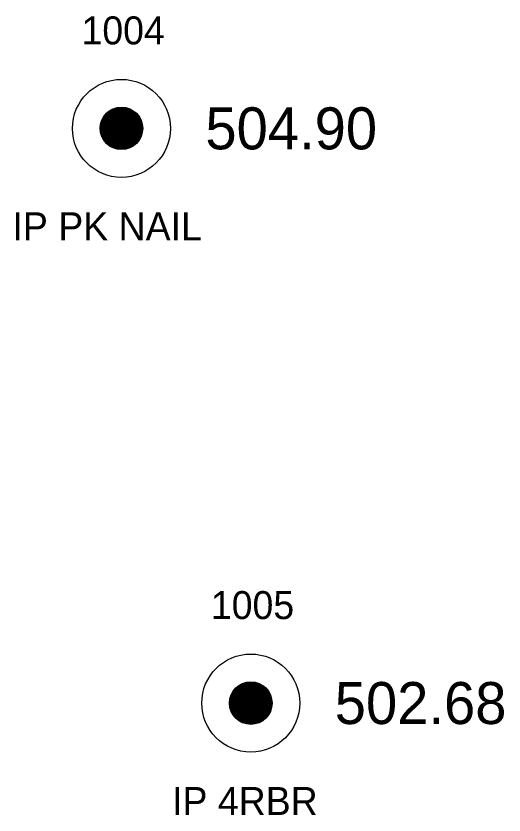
# Model space of a CAD drawing. Extents: x 1754677 to 1756729, y 972996 to 978369.
# Drawn here: x 1755719.06 to 1755736.5, y 978340.61 to 978369.16 of the extents above; entities that cross this region are included whole.
import ezdxf

# ---------------------------------------------------------------- set-up
doc = ezdxf.new("R2010")
doc.units = 0
for name, color, linetype in [('RD_EX_DV_Prop_txCode', 7, 'Continuous'), ('RD_EX_DV_PropPin', 7, 'Continuous'), ('RD_EX_TX_DV_Prop_ELEV', 7, 'Continuous'), ('RD_SMD_Locator', 7, 'Continuous')]:
    doc.layers.add(name, color=color, linetype=linetype)

msp = doc.modelspace()

# ---------------------------------------------------------------- linework, layer by layer
at = {"layer": 'RD_EX_DV_PropPin'}
for p, q in [((1755722.408, 978364.508), (1755722.408, 978365.777)), ((1755722.443, 978364.486), (1755722.443, 978365.799)), ((1755722.478, 978364.467), (1755722.478, 978365.818)), ((1755722.513, 978364.45), (1755722.513, 978365.836)), ((1755722.548, 978364.435), (1755722.548, 978365.85)), ((1755722.583, 978364.422), (1755722.583, 978365.863)), ((1755722.618, 978364.411), (1755722.618, 978365.874)), ((1755722.653, 978364.402), (1755722.653, 978365.883)), ((1755722.688, 978364.395), (1755722.688, 978365.891)), ((1755722.723, 978364.389), (1755722.723, 978365.897)), ((1755722.758, 978364.385), (1755722.758, 978365.901)), ((1755722.793, 978364.383), (1755722.793, 978365.903)), ((1755722.828, 978364.382), (1755722.828, 978365.904)), ((1755722.863, 978364.383), (1755722.863, 978365.903)), ((1755722.898, 978364.385), (1755722.898, 978365.901)), ((1755722.933, 978364.389), (1755722.933, 978365.897)), ((1755722.968, 978364.395), (1755722.968, 978365.891)), ((1755723.003, 978364.402), (1755723.003, 978365.883)), ((1755723.038, 978364.411), (1755723.038, 978365.874)), ((1755723.073, 978364.422), (1755723.073, 978365.863)), ((1755723.108, 978364.435), (1755723.108, 978365.85)), ((1755723.143, 978364.45), (1755723.143, 978365.836)), ((1755723.178, 978364.467), (1755723.178, 978365.818)), ((1755723.213, 978364.486), (1755723.213, 978365.799)), ((1755723.248, 978364.508), (1755723.248, 978365.777)), ((1755722.162, 978364.773), (1755722.162, 978365.512)), ((1755722.197, 978364.716), (1755722.197, 978365.569)), ((1755722.232, 978364.669), (1755722.232, 978365.617)), ((1755722.267, 978364.628), (1755722.267, 978365.658)), ((1755722.302, 978364.592), (1755722.302, 978365.694)), ((1755722.337, 978364.561), (1755722.337, 978365.725)), ((1755722.372, 978364.533), (1755722.372, 978365.753)), ((1755723.283, 978364.533), (1755723.283, 978365.753)), ((1755723.318, 978364.561), (1755723.318, 978365.725)), ((1755723.353, 978364.592), (1755723.353, 978365.694)), ((1755723.388, 978364.628), (1755723.388, 978365.658)), ((1755723.423, 978364.669), (1755723.423, 978365.617)), ((1755723.458, 978364.716), (1755723.458, 978365.569)), ((1755723.493, 978364.773), (1755723.493, 978365.512)), ((1755722.092, 978364.947), (1755722.092, 978365.339)), ((1755722.127, 978364.845), (1755722.127, 978365.441)), ((1755723.528, 978364.845), (1755723.528, 978365.441)), ((1755723.563, 978364.947), (1755723.563, 978365.339)), ((1755727.03, 978343.977), (1755727.03, 978345.246)), ((1755727.065, 978343.955), (1755727.065, 978345.267)), ((1755727.1, 978343.935), (1755727.1, 978345.287)), ((1755727.135, 978343.918), (1755727.135, 978345.304)), ((1755727.17, 978343.904), (1755727.17, 978345.319)), ((1755727.205, 978343.891), (1755727.205, 978345.332)), ((1755727.24, 978343.88), (1755727.24, 978345.343)), ((1755727.275, 978343.87), (1755727.275, 978345.352)), ((1755727.31, 978343.863), (1755727.31, 978345.359)), ((1755727.345, 978343.857), (1755727.345, 978345.365)), ((1755727.38, 978343.853), (1755727.38, 978345.369)), ((1755727.415, 978343.851), (1755727.415, 978345.371)), ((1755727.45, 978343.85), (1755727.45, 978345.372)), ((1755727.485, 978343.851), (1755727.485, 978345.371)), ((1755727.52, 978343.853), (1755727.52, 978345.369)), ((1755727.555, 978343.857), (1755727.555, 978345.365)), ((1755727.59, 978343.863), (1755727.59, 978345.359)), ((1755727.625, 978343.87), (1755727.625, 978345.352)), ((1755727.66, 978343.88), (1755727.66, 978345.343)), ((1755727.695, 978343.891), (1755727.695, 978345.332)), ((1755727.73, 978343.904), (1755727.73, 978345.319)), ((1755727.765, 978343.918), (1755727.765, 978345.304)), ((1755727.8, 978343.935), (1755727.8, 978345.287)), ((1755727.835, 978343.955), (1755727.835, 978345.267)), ((1755727.87, 978343.977), (1755727.87, 978345.246)), ((1755726.785, 978344.242), (1755726.785, 978344.981)), ((1755726.82, 978344.185), (1755726.82, 978345.038)), ((1755726.855, 978344.137), (1755726.855, 978345.085)), ((1755726.89, 978344.096), (1755726.89, 978345.126)), ((1755726.925, 978344.06), (1755726.925, 978345.162)), ((1755726.96, 978344.029), (1755726.96, 978345.193)), ((1755726.995, 978344.001), (1755726.995, 978345.221)), ((1755727.905, 978344.001), (1755727.905, 978345.221)), ((1755727.94, 978344.029), (1755727.94, 978345.193)), ((1755727.975, 978344.06), (1755727.975, 978345.162)), ((1755728.01, 978344.096), (1755728.01, 978345.126)), ((1755728.045, 978344.137), (1755728.045, 978345.085)), ((1755728.08, 978344.185), (1755728.08, 978345.038)), ((1755728.115, 978344.242), (1755728.115, 978344.981)), ((1755726.715, 978344.415), (1755726.715, 978344.807)), ((1755726.75, 978344.313), (1755726.75, 978344.909)), ((1755728.15, 978344.313), (1755728.15, 978344.909)), ((1755728.185, 978344.415), (1755728.185, 978344.807))]:
    msp.add_line(p, q, dxfattribs=at)
for centre, radius in [((1755722.828, 978365.143), 1.75), ((1755722.828, 978365.143), 0.761), ((1755727.45, 978344.611), 1.75), ((1755727.45, 978344.611), 0.761)]:
    msp.add_circle(centre, radius, dxfattribs=at)
at = {"layer": 'RD_SMD_Locator'}
for centre in [(1755722.828, 978365.143), (1755727.45, 978344.611)]:
    msp.add_circle(centre, 0.15, dxfattribs=at)

# ---------------------------------------------------------------- texts
at = {"layer": 'RD_EX_DV_Prop_txCode'}
for s, p in [('1004', (1755721.403, 978368.143)), ('IP PK NAIL', (1755718.938, 978361.143)), ('1005', (1755726.025, 978347.611)), ('IP 4RBR', (1755724.639, 978340.611))]:
    msp.add_text(s, height=1, dxfattribs=at).set_placement(p)
at = {"layer": 'RD_EX_TX_DV_Prop_ELEV'}
for s, p in [('504.90', (1755725.828, 978364.393)), ('502.68', (1755730.45, 978343.861))]:
    msp.add_text(s, height=1.5, dxfattribs=at).set_placement(p)

doc.saveas('drawing.dxf')
